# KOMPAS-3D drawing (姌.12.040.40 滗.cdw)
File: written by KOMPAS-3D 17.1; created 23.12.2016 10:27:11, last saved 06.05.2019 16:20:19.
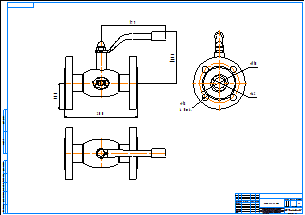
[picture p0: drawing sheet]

Sheet 1: A1, landscape

Title block, sheet 1: name: КШ.12.040.40 фф; material: Внимание! Данный продукт является объектом авторского права ООО «Торговый Дом АДЛ». / Запрещается изменение, копирование, распространение / (в том числе путем копирования на другие сайты и ресурсы в Интернете) / или любое иное использование информации и объектов без предварительного / согласия правообладателя (ООО «Торговый Дом АДЛ»).; sheets: 1; organisation: ООО "Торговый дом АДЛ"; sheet format: A1; stored path: C:\Users\tra\Desktop\2д чертежи\Шаровые краны БИВАЛ\КШ_Бивал_серия_11_12\KOMPAS_2D\КШ.12.040.40 фф.cdw

Views: Вид 1, Проекционный вид 2, Проекционный вид 3
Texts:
  Klimkovich
  ADL
Dimensions and other numbers on the sheet: 200; 142,6; 179; 72,5; 110; 42; 18; 4 Отв.; 1:1; 1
